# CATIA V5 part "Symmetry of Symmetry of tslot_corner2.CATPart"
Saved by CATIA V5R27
Part number: Symmetry of Symmetry of tslot_corner2
Bounding box of the stored display mesh (mm): x -19.05 to 19.05, y -19.05 to 19.05, z -1374.764 to -1219.2
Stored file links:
  \\triton.meca.polymtl.ca\usagers\zaoue\profiles\Desktop\varm_ass\structure prismatique\Symmetry of Symmetry of tslot_corner2.CATPart
  \\triton.meca.polymtl.ca\usagers\zaoue\profiles\Desktop\varm_ass\structure prismatique\Symmetry of tslot_corner2.CATPart
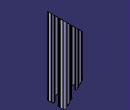
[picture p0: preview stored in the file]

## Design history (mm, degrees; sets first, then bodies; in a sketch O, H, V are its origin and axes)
Body1 (main body)
Body2 "Boss-Extrude1"
  Solid1: linked copy from another document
